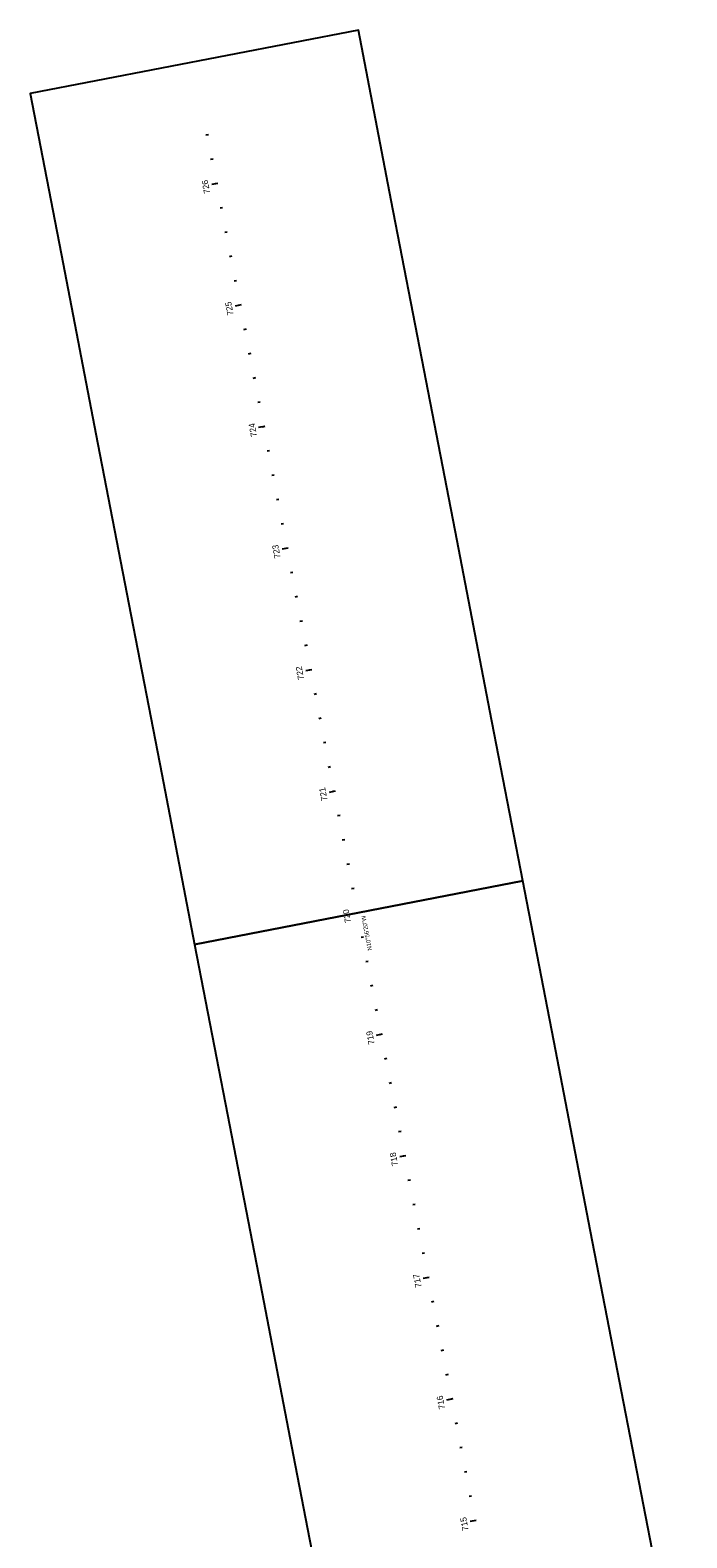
# Model space of a CAD drawing. Extents: x 2005522 to 2006988, y 402476 to 404900.
# Drawn here: x 2005522 to 2006052, y 403682 to 404900 of the extents above; entities that cross this region are included whole.
import ezdxf

# ---------------------------------------------------------------- set-up
doc = ezdxf.new("R2010")
doc.units = 0
for name, color, linetype in [('ClipDrawingBound_dp', 7, 'Continuous'), ('TextAlgnStation100', 7, 'Continuous'), ('TextAlgnStation1000', 7, 'Continuous'), ('TextAlgnStation500', 7, 'Continuous'), ('TextAlgnTangent', 7, 'Continuous'), ('TextAlgnTicks100', 7, 'Continuous'), ('TextAlgnTicks1000', 7, 'Continuous'), ('TextAlgnTicks500', 7, 'Continuous'), ('TextAlgnTicks5000', 7, 'Continuous')]:
    doc.layers.add(name, color=color, linetype=linetype)

msp = doc.modelspace()

# ---------------------------------------------------------------- linework, layer by layer
at = {"layer": 'ClipDrawingBound_dp'}
for points in [[(2005654.4, 404161.3), (2005919.5, 404212.5), (2005892.9, 404350), (2005866.4, 404487.4), (2005839.8, 404624.9), (2005813.2, 404762.3), (2005786.7, 404899.8), (2005521.6, 404848.5), (2005548.1, 404711.1), (2005574.7, 404573.6), (2005601.3, 404436.2), (2005627.8, 404298.7)], [(2005788.4, 403470.3), (2006051.9, 403529), (2006025.8, 403662.7), (2005999.2, 403800.1), (2005972.6, 403937.6), (2005946.1, 404075), (2005919.5, 404212.5), (2005654.4, 404161.3), (2005681, 404023.8), (2005707.5, 403886.3), (2005734.1, 403748.9), (2005760.7, 403611.4)]]:
    msp.add_lwpolyline(points, close=True, dxfattribs=at)
at = {"layer": 'TextAlgnTicks100'}
for p, q in [((2005665.5, 404815.2), (2005663.5, 404814.9)), ((2005669.3, 404795.6), (2005667.3, 404795.2)), ((2005673.1, 404776), (2005668.2, 404775)), ((2005676.9, 404756.3), (2005674.9, 404756)), ((2005680.7, 404736.7), (2005678.7, 404736.3)), ((2005684.5, 404717.1), (2005682.5, 404716.7)), ((2005688.3, 404697.4), (2005686.3, 404697)), ((2005692.1, 404677.8), (2005687.2, 404676.8)), ((2005695.9, 404658.2), (2005693.9, 404657.8)), ((2005699.7, 404638.5), (2005697.7, 404638.1)), ((2005703.5, 404618.9), (2005701.5, 404618.5)), ((2005707.2, 404599.2), (2005705.3, 404598.9)), ((2005711, 404579.6), (2005706.1, 404578.7)), ((2005714.8, 404560), (2005712.9, 404559.6)), ((2005718.6, 404540.3), (2005716.7, 404540)), ((2005722.4, 404520.7), (2005720.5, 404520.3)), ((2005726.2, 404501.1), (2005724.3, 404500.7)), ((2005730, 404481.4), (2005725.1, 404480.5)), ((2005733.8, 404461.8), (2005731.9, 404461.4)), ((2005737.6, 404442.2), (2005735.6, 404441.8)), ((2005741.4, 404422.5), (2005739.4, 404422.1)), ((2005745.2, 404402.9), (2005743.2, 404402.5)), ((2005749, 404383.2), (2005744.1, 404382.3)), ((2005752.8, 404363.6), (2005750.8, 404363.2)), ((2005756.6, 404344), (2005754.6, 404343.6)), ((2005760.4, 404324.3), (2005758.4, 404324)), ((2005764.2, 404304.7), (2005762.2, 404304.3)), ((2005768, 404285.1), (2005763.1, 404284.1)), ((2005771.8, 404265.4), (2005769.8, 404265)), ((2005775.6, 404245.8), (2005773.6, 404245.4)), ((2005779.4, 404226.2), (2005777.4, 404225.8)), ((2005783.2, 404206.5), (2005781.2, 404206.1)), ((2005786.9, 404186.9), (2005782, 404185.9)), ((2005790.7, 404167.2), (2005788.8, 404166.9)), ((2005794.5, 404147.6), (2005792.6, 404147.2)), ((2005798.3, 404128), (2005796.4, 404127.6)), ((2005802.1, 404108.3), (2005800.2, 404108)), ((2005805.9, 404088.7), (2005801, 404087.7)), ((2005809.7, 404069.1), (2005807.8, 404068.7)), ((2005813.5, 404049.4), (2005811.6, 404049)), ((2005817.3, 404029.8), (2005815.3, 404029.4)), ((2005821.1, 404010.1), (2005819.1, 404009.8)), ((2005824.9, 403990.5), (2005820, 403989.6)), ((2005828.7, 403970.9), (2005826.7, 403970.5)), ((2005832.5, 403951.2), (2005830.5, 403950.9)), ((2005836.3, 403931.6), (2005834.3, 403931.2)), ((2005840.1, 403912), (2005838.1, 403911.6)), ((2005843.9, 403892.3), (2005839, 403891.4)), ((2005847.7, 403872.7), (2005845.7, 403872.3)), ((2005851.5, 403853.1), (2005849.5, 403852.7)), ((2005855.3, 403833.4), (2005853.3, 403833)), ((2005859.1, 403813.8), (2005857.1, 403813.4)), ((2005862.9, 403794.1), (2005857.9, 403793.2)), ((2005866.6, 403774.5), (2005864.7, 403774.1)), ((2005870.4, 403754.9), (2005868.5, 403754.5)), ((2005874.2, 403735.2), (2005872.3, 403734.9)), ((2005878, 403715.6), (2005876.1, 403715.2)), ((2005881.8, 403696), (2005876.9, 403695))]:
    msp.add_line(p, q, dxfattribs=at)
at = {"layer": 'TextAlgnTicks1000'}
for p, q in [((2005673.1, 404776), (2005671.1, 404775.6)), ((2005711, 404579.6), (2005709.1, 404579.2)), ((2005749, 404383.2), (2005747, 404382.9)), ((2005786.9, 404186.9), (2005782, 404185.9)), ((2005824.9, 403990.5), (2005822.9, 403990.1)), ((2005862.9, 403794.1), (2005860.9, 403793.8))]:
    msp.add_line(p, q, dxfattribs=at)
at = {"layer": 'TextAlgnTicks500'}
for p, q in [((2005673.1, 404776), (2005671.1, 404775.6)), ((2005692.1, 404677.8), (2005687.2, 404676.8)), ((2005711, 404579.6), (2005709.1, 404579.2)), ((2005730, 404481.4), (2005728.1, 404481)), ((2005749, 404383.2), (2005747, 404382.9)), ((2005768, 404285.1), (2005766, 404284.7)), ((2005786.9, 404186.9), (2005782, 404185.9)), ((2005805.9, 404088.7), (2005804, 404088.3)), ((2005824.9, 403990.5), (2005822.9, 403990.1)), ((2005843.9, 403892.3), (2005841.9, 403891.9)), ((2005862.9, 403794.1), (2005860.9, 403793.8)), ((2005881.8, 403696), (2005876.9, 403695))]:
    msp.add_line(p, q, dxfattribs=at)
at = {"layer": 'TextAlgnTicks5000'}
msp.add_line((2005786.9, 404186.9), (2005785, 404186.5), dxfattribs=at)

# ---------------------------------------------------------------- texts
at = {"layer": 'TextAlgnStation100'}
for s, p in [('726', (2005667, 404768.2)), ('725', (2005685.9, 404669.9)), ('724', (2005704.9, 404571.8)), ('723', (2005723.9, 404473.6)), ('722', (2005742.9, 404375.4)), ('721', (2005761.8, 404277.6)), ('720', (2005780.8, 404179.1)), ('719', (2005799.8, 404080.9)), ('718', (2005818.8, 403982.7)), ('717', (2005837.7, 403884.6)), ('716', (2005856.7, 403786.3)), ('715', (2005875.7, 403688.1))]:
    msp.add_text(s, height=4.98, rotation=100.9389, dxfattribs=at).set_placement(p)
at = {"layer": 'TextAlgnStation1000'}
msp.add_text('720', height=4.98, rotation=100.9389, dxfattribs=at).set_placement((2005780.8, 404179.1))
at = {"layer": 'TextAlgnStation500'}
for s, p in [('725', (2005685.9, 404669.9)), ('720', (2005780.8, 404179.1)), ('715', (2005875.7, 403688.1))]:
    msp.add_text(s, height=4.98, rotation=100.9389, dxfattribs=at).set_placement(p)
at = {"layer": 'TextAlgnTangent'}
msp.add_text('N10°56\'20"W', height=3.48, rotation=100.9389, dxfattribs=at).set_placement((2005797.7, 404156.7))

doc.saveas('drawing.dxf')
